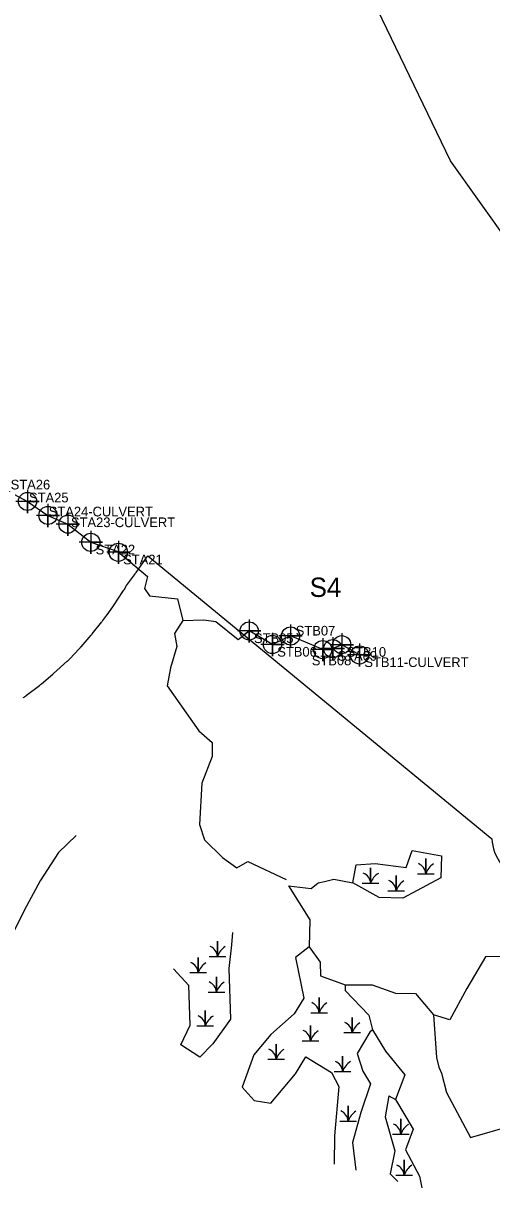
# Model space of a CAD drawing. Extents: x 1253697 to 1278588, y 912189 to 981699.
# Drawn here: x 1260180 to 1260665, y 913254 to 914458 of the extents above; entities that cross this region are included whole.
import ezdxf

# ---------------------------------------------------------------- set-up
doc = ezdxf.new("R2010")
doc.units = 0
for name, color, linetype in [('Default', 7, 'Continuous'), ('Exist Environmental Wetland Boundary', 7, 'Continuous'), ('Exist Environmental Wetland Boundary Cogo Number', 7, 'Continuous'), ('Exist Hydro Jurisdictional Stream or Body of Water Mitigable', 7, 'Continuous'), ('Exist Hydro Jurisdictional Stream or Body of Water Mitigable Cogo Comment', 7, 'Continuous'), ('Exist Hydro Jurisdictional Stream or Body of Water Mitigable Cogo Point CELL', 7, 'Continuous'), ('Exist Hydro Swamp or Marsh', 7, 'Continuous')]:
    doc.layers.add(name, color=color, linetype=linetype)

msp = doc.modelspace()

# ---------------------------------------------------------------- linework, layer by layer
at = {"layer": 'Default'}
for p, q in [((1260273.8, 913856.5), (1260282.9, 913870.4)), ((1260273.8, 913856.5), (1260282.9, 913870.4)), ((1260273.8, 913856.5), (1260282.9, 913870.4)), ((1260273.8, 913856.5), (1260282.9, 913870.4)), ((1260262.1, 913840.4), (1260266.1, 913845.8)), ((1260262.1, 913840.4), (1260266.1, 913845.8)), ((1260262.1, 913840.4), (1260266.1, 913845.8)), ((1260262.1, 913840.4), (1260266.1, 913845.8)), ((1260266.4, 913846.3), (1260272.4, 913854.5)), ((1260266.4, 913846.3), (1260272.4, 913854.5)), ((1260266.4, 913846.3), (1260272.4, 913854.5)), ((1260266.4, 913846.3), (1260272.4, 913854.5)), ((1260251.1, 913826.6), (1260261.1, 913839.1)), ((1260251.1, 913826.6), (1260261.1, 913839.1)), ((1260251.1, 913826.6), (1260261.1, 913839.1)), ((1260251.1, 913826.6), (1260261.1, 913839.1)), ((1260239.6, 913813.1), (1260249.9, 913825.2)), ((1260239.6, 913813.1), (1260249.9, 913825.2)), ((1260239.6, 913813.1), (1260249.9, 913825.2)), ((1260239.6, 913813.1), (1260249.9, 913825.2)), ((1260227.8, 913800.7), (1260237.7, 913811.1)), ((1260227.8, 913800.7), (1260237.7, 913811.1)), ((1260227.8, 913800.7), (1260237.7, 913811.1)), ((1260227.8, 913800.7), (1260237.7, 913811.1)), ((1260211, 913785.5), (1260225, 913798.1)), ((1260211, 913785.5), (1260225, 913798.1)), ((1260211, 913785.5), (1260225, 913798.1)), ((1260211, 913785.5), (1260225, 913798.1)), ((1260198.5, 913774.8), (1260210.2, 913784.8)), ((1260198.5, 913774.8), (1260210.2, 913784.8)), ((1260198.5, 913774.8), (1260210.2, 913784.8)), ((1260198.5, 913774.8), (1260210.2, 913784.8)), ((1260183.2, 913763), (1260196.4, 913773.2)), ((1260183.2, 913763), (1260196.4, 913773.2)), ((1260183.2, 913763), (1260196.4, 913773.2)), ((1260183.2, 913763), (1260196.4, 913773.2))]:
    msp.add_line(p, q, dxfattribs=at)
for points in [[(1261126.9, 913832.3), (1260885, 914025.7), (1260783.1, 914115.2), (1260719.8, 914184.5), (1260681.8, 914231.6), (1260621.8, 914315.9), (1260490.2, 914589.2), (1260463.9, 914685.8), (1260447.7, 914764), (1260445.4, 914777.7), (1260444.3, 914785.1), (1260438.9, 914823.1), (1260433.3, 914875.8), (1260429.6, 914955.5), (1260430.1, 914996.6), (1260457.3, 915231.6)], [(1261126.9, 913832.3), (1260885, 914025.7), (1260783.1, 914115.2), (1260719.8, 914184.5), (1260681.8, 914231.6), (1260621.8, 914315.9), (1260490.2, 914589.2), (1260463.9, 914685.8), (1260447.7, 914764), (1260445.4, 914777.7), (1260444.3, 914785.1), (1260438.9, 914823.1), (1260433.3, 914875.8), (1260429.6, 914955.5), (1260430.1, 914996.6), (1260457.3, 915231.6)], [(1261126.9, 913832.3), (1260885, 914025.7), (1260783.1, 914115.2), (1260719.8, 914184.5), (1260681.8, 914231.6), (1260621.8, 914315.9), (1260490.2, 914589.2), (1260463.9, 914685.8), (1260447.7, 914764), (1260445.4, 914777.7), (1260444.3, 914785.1), (1260438.9, 914823.1), (1260433.3, 914875.8), (1260429.6, 914955.5), (1260430.1, 914996.6), (1260457.3, 915231.6)], [(1261126.9, 913832.3), (1260885, 914025.7), (1260783.1, 914115.2), (1260719.8, 914184.5), (1260681.8, 914231.6), (1260621.8, 914315.9), (1260490.2, 914589.2), (1260463.9, 914685.8), (1260447.7, 914764), (1260445.4, 914777.7), (1260444.3, 914785.1), (1260438.9, 914823.1), (1260433.3, 914875.8), (1260429.6, 914955.5), (1260430.1, 914996.6), (1260457.3, 915231.6)], [(1260296.5, 913890), (1260308.6, 913907.1), (1260664.5, 913614.5)], [(1260296.5, 913890), (1260308.6, 913907.1), (1260664.5, 913614.5)], [(1260296.5, 913890), (1260308.6, 913907.1), (1260664.5, 913614.5)], [(1260296.5, 913890), (1260308.6, 913907.1), (1260664.5, 913614.5)], [(1260284, 913872.1), (1260286.6, 913876.6), (1260295.9, 913889.1)], [(1260284, 913872.1), (1260286.6, 913876.6), (1260295.9, 913889.1)], [(1260284, 913872.1), (1260286.6, 913876.6), (1260295.9, 913889.1)], [(1260284, 913872.1), (1260286.6, 913876.6), (1260295.9, 913889.1)]]:
    msp.add_lwpolyline(points, dxfattribs=at)
for centre, start, end in [((1260255.7, 913918.9), 323.5537, 324.7668), ((1260255.7, 913918.9), 323.5537, 324.7668), ((1260255.7, 913918.9), 323.5537, 324.7668), ((1260255.7, 913918.9), 323.5537, 324.7668), ((1260241, 913897.8), 326.8185, 329.1489), ((1260241, 913897.8), 326.8185, 329.1489), ((1260241, 913897.8), 326.8185, 329.1489), ((1260241, 913897.8), 326.8185, 329.1489), ((1260226, 913875.7), 323.3471, 323.9808), ((1260226, 913875.7), 323.3471, 323.9808), ((1260226, 913875.7), 323.3471, 323.9808), ((1260226, 913875.7), 323.3471, 323.9808), ((1260231.9, 913883.9), 323.9808, 326.8185), ((1260231.9, 913883.9), 323.9808, 326.8185), ((1260231.9, 913883.9), 323.9808, 326.8185), ((1260231.9, 913883.9), 323.9808, 326.8185), ((1260221.9, 913870.3), 321.4621, 323.3471), ((1260221.9, 913870.3), 321.4621, 323.3471), ((1260221.9, 913870.3), 321.4621, 323.3471), ((1260221.9, 913870.3), 321.4621, 323.3471), ((1260212, 913857.8), 319.3323, 321.4621), ((1260212, 913857.8), 319.3323, 321.4621), ((1260212, 913857.8), 319.3323, 321.4621), ((1260212, 913857.8), 319.3323, 321.4621), ((1260201.6, 913845.7), 316.2099, 319.3323), ((1260201.6, 913845.7), 316.2099, 319.3323), ((1260201.6, 913845.7), 316.2099, 319.3323), ((1260201.6, 913845.7), 316.2099, 319.3323), ((1260191.7, 913835.3), 311.8111, 316.2099), ((1260191.7, 913835.3), 311.8111, 316.2099), ((1260191.7, 913835.3), 311.8111, 316.2099), ((1260191.7, 913835.3), 311.8111, 316.2099), ((1260166, 913812.9), 307.4467, 310.5316), ((1260166, 913812.9), 307.4467, 310.5316), ((1260166, 913812.9), 307.4467, 310.5316), ((1260166, 913812.9), 307.4467, 310.5316), ((1260177.7, 913822.8), 310.5316, 311.8111), ((1260177.7, 913822.8), 310.5316, 311.8111), ((1260177.7, 913822.8), 310.5316, 311.8111), ((1260177.7, 913822.8), 310.5316, 311.8111), ((1260152.8, 913802.7), 302.5799, 307.4467), ((1260152.8, 913802.7), 302.5799, 307.4467), ((1260152.8, 913802.7), 302.5799, 307.4467), ((1260152.8, 913802.7), 302.5799, 307.4467), ((1260714.4, 913618.1), 184.1324, 216.2345), ((1260714.4, 913618.1), 184.1324, 216.2345), ((1260714.4, 913618.1), 184.1324, 216.2345), ((1260714.4, 913618.1), 184.1324, 216.2345)]:
    msp.add_arc(centre, 50, start, end, dxfattribs=at)
at = {"layer": 'Exist Environmental Wetland Boundary'}
msp.add_lwpolyline([(1260524.1, 913587.6), (1260543.9, 913589.1), (1260575.8, 913584.8), (1260582.1, 913602.3), (1260597.3, 913599.8), (1260612.4, 913596.8), (1260611.8, 913574), (1260572.5, 913553), (1260548.1, 913553.7), (1260520.8, 913568.8)], close=True, dxfattribs=at)
for points in [[(1260396.1, 913517.6), (1260395.3, 913504.9), (1260392.5, 913480.4), (1260394.2, 913428), (1260375.9, 913402.5), (1260362.6, 913388.6), (1260342.9, 913401.5), (1260352.3, 913421.9), (1260351.2, 913462.9), (1260335.2, 913479.9)], [(1260475.5, 913502.8), (1260461.4, 913491.8), (1260470.1, 913449.8), (1260460.1, 913433.4), (1260436, 913412), (1260418.2, 913391), (1260406.2, 913357.6), (1260418.6, 913343.8), (1260436, 913341), (1260461.5, 913371.4), (1260472, 913388.9), (1260498.6, 913372.7), (1260506.3, 913358.3), (1260501.7, 913307.2), (1260501.5, 913277.9)], [(1260475.5, 913502.8), (1260486.9, 913487), (1260487.3, 913472.9), (1260512.9, 913463.5), (1260512.7, 913457.6), (1260537.3, 913432.2), (1260541.1, 913416.8), (1260538.4, 913414.5), (1260525.2, 913392.6), (1260531.2, 913374), (1260539.2, 913361.1), (1260529.1, 913331.4), (1260520.5, 913300.3), (1260523.8, 913271.9)], [(1260558.1, 913348.8), (1260554.3, 913326.9), (1260564.2, 913291.8), (1260559.3, 913268.1), (1260567.4, 913260.2)], [(1260558.1, 913348.8), (1260565.1, 913344.9), (1260583.2, 913314.3), (1260575.4, 913292.7), (1260589.6, 913265.6), (1260592.2, 913253.6)]]:
    msp.add_lwpolyline(points, dxfattribs=at)
at = {"layer": 'Exist Hydro Jurisdictional Stream or Body of Water Mitigable'}
msp.add_line((1260226.5, 913939.5), (1260225.9, 913940), dxfattribs=at)
for points in [[(1259903.1, 914152.4), (1259926.1, 914135.1), (1259928.5, 914122.8), (1259949.5, 914108.7), (1259980.6, 914083.6), (1260018, 914066.7), (1260046.6, 914049.7), (1260057.3, 914045.6), (1260102.1, 914011.9), (1260111.8, 914005.5), (1260128.8, 913997.3), (1260160.9, 913975.8), (1260184.1, 913963.5), (1260205.3, 913949), (1260226.5, 913939.5)], [(1260225.9, 913940), (1260249.6, 913921.2), (1260277.7, 913911.8), (1260299.1, 913893.7)], [(1260225.9, 913940), (1260249.6, 913921.2), (1260277.7, 913911.8), (1260308.2, 913886), (1260305.3, 913873.4), (1260310.3, 913865.9), (1260339.2, 913862.6), (1260344.8, 913840.2), (1260366.7, 913841.1), (1260379, 913839.2), (1260402.2, 913820.8), (1260413.5, 913829.5)], [(1260344.8, 913840.2), (1260336.3, 913826.9), (1260338.6, 913813.4), (1260332.1, 913791.2), (1260328.7, 913772.7), (1260361.3, 913726.3), (1260375.2, 913714.1), (1260375.2, 913699.8), (1260364.6, 913672), (1260362.2, 913629.3), (1260367.3, 913613.5), (1260385.9, 913595.1), (1260400.9, 913584.4), (1260412.1, 913590.9), (1260451.7, 913572.3)], [(1260527.7, 913804.7), (1260509.3, 913815.3), (1260500, 913811.2), (1260489.6, 913810.2), (1260456.3, 913824.3), (1260437.6, 913815.5), (1260413.5, 913829.5), (1260408.1, 913825.3)], [(1260234.6, 913618.1), (1260216.1, 913600.4), (1260197.1, 913571.1), (1260180.6, 913540.3), (1260165.8, 913510.5), (1260157.4, 913474.6), (1260147.6, 913437.2), (1260126.5, 913405.4), (1260109.1, 913382.8)], [(1260454.1, 913565.7), (1260477.7, 913563.2), (1260484.8, 913569), (1260491.5, 913570.4), (1260501.2, 913572.9), (1260520.8, 913568.8)], [(1260454.1, 913565.7), (1260476.4, 913530.7), (1260475.5, 913502.8), (1260486.9, 913487), (1260487.3, 913472.9), (1260512.9, 913463.5), (1260540.9, 913463.4), (1260565, 913454.8), (1260585.6, 913454.5), (1260604.3, 913432.3), (1260607.2, 913388.4), (1260609.8, 913378.3), (1260612.6, 913372.1), (1260617.6, 913352.2), (1260642.4, 913305.6), (1260685.8, 913317.8), (1260734.5, 913312.3), (1260786.9, 913302.3), (1260809.8, 913272)], [(1260774.9, 913564.6), (1260768.5, 913557.3), (1260740.4, 913548.2), (1260720.4, 913537.4), (1260696.9, 913522.2), (1260688.7, 913492.8), (1260658.1, 913492.3), (1260638.7, 913459.6), (1260621, 913427.1), (1260604.3, 913432.3)], [(1260512.7, 913457.6), (1260537.3, 913432.2), (1260541.1, 913416.8), (1260554.5, 913395), (1260574.5, 913370.4), (1260565.1, 913344.9)], [(1260541.1, 913416.8), (1260538.4, 913414.5), (1260525.2, 913392.6), (1260531.2, 913374)]]:
    msp.add_lwpolyline(points, dxfattribs=at)
at = {"layer": 'Exist Hydro Jurisdictional Stream or Body of Water Mitigable Cogo Point CELL'}
for points in [[(1260184.1, 913975.5), (1260184.1, 913951.5), (1260184.1, 913963.5), (1260196.1, 913963.5), (1260172.1, 913963.5)], [(1260184.1, 913975.5), (1260184.1, 913951.5), (1260184.1, 913963.5), (1260196.1, 913963.5), (1260172.1, 913963.5)], [(1260205.3, 913961), (1260205.3, 913937), (1260205.3, 913949), (1260217.3, 913949), (1260193.3, 913949)], [(1260205.3, 913961), (1260205.3, 913937), (1260205.3, 913949), (1260217.3, 913949), (1260193.3, 913949)], [(1260225.9, 913952), (1260225.9, 913928), (1260225.9, 913940), (1260237.9, 913940), (1260213.9, 913940)], [(1260225.9, 913952), (1260225.9, 913928), (1260225.9, 913940), (1260237.9, 913940), (1260213.9, 913940)], [(1260249.6, 913933.2), (1260249.6, 913909.2), (1260249.6, 913921.2), (1260261.6, 913921.2), (1260237.6, 913921.2)], [(1260249.6, 913933.2), (1260249.6, 913909.2), (1260249.6, 913921.2), (1260261.6, 913921.2), (1260237.6, 913921.2)], [(1260278.1, 913922.9), (1260278.1, 913898.9), (1260278.1, 913910.9), (1260290.1, 913910.9), (1260266.1, 913910.9)], [(1260278.1, 913922.9), (1260278.1, 913898.9), (1260278.1, 913910.9), (1260290.1, 913910.9), (1260266.1, 913910.9)], [(1260413.5, 913841.5), (1260413.5, 913817.5), (1260413.5, 913829.5), (1260425.5, 913829.5), (1260401.5, 913829.5)], [(1260456.3, 913836.3), (1260456.3, 913812.3), (1260456.3, 913824.3), (1260468.3, 913824.3), (1260444.3, 913824.3)], [(1260437.6, 913827.5), (1260437.6, 913803.5), (1260437.6, 913815.5), (1260449.6, 913815.5), (1260425.6, 913815.5)], [(1260489.6, 913822.2), (1260489.6, 913798.2), (1260489.6, 913810.2), (1260501.6, 913810.2), (1260477.6, 913810.2)], [(1260500, 913823.2), (1260500, 913799.2), (1260500, 913811.2), (1260512, 913811.2), (1260488, 913811.2)], [(1260509.3, 913827.3), (1260509.3, 913803.3), (1260509.3, 913815.3), (1260521.3, 913815.3), (1260497.3, 913815.3)], [(1260527.7, 913816.7), (1260527.7, 913792.7), (1260527.7, 913804.7), (1260539.7, 913804.7), (1260515.7, 913804.7)]]:
    msp.add_lwpolyline(points, dxfattribs=at)
for centre in [(1260184.1, 913963.5), (1260184.1, 913963.5), (1260205.3, 913949), (1260205.3, 913949), (1260225.9, 913940), (1260225.9, 913940), (1260249.6, 913921.2), (1260249.6, 913921.2), (1260278.1, 913910.9), (1260278.1, 913910.9), (1260413.5, 913829.5), (1260437.6, 913815.5), (1260456.3, 913824.3), (1260509.3, 913815.3), (1260489.6, 913810.2), (1260500, 913811.2), (1260527.7, 913804.7)]:
    msp.add_circle(centre, 9.38, dxfattribs=at)
at = {"layer": 'Exist Hydro Swamp or Marsh'}
for p, q in [((1260596.3, 913585.5), (1260596.3, 913585.5)), ((1260539.2, 913575.7), (1260539.2, 913575.7)), ((1260565.6, 913568), (1260565.6, 913568)), ((1260380.7, 913499.9), (1260380.7, 913499.9)), ((1260360.7, 913483.2), (1260360.7, 913483.2)), ((1260379.6, 913463.1), (1260379.6, 913463.1)), ((1260485.8, 913441.8), (1260485.8, 913441.8)), ((1260368.1, 913428.1), (1260368.1, 913428.1)), ((1260476.9, 913412.8), (1260476.9, 913412.8)), ((1260520, 913421.1), (1260520, 913421.1)), ((1260441.4, 913393.6), (1260441.4, 913393.6)), ((1260510.2, 913381), (1260510.2, 913381)), ((1260516, 913329.6), (1260516, 913329.6)), ((1260570.4, 913316.1), (1260570.4, 913316.1)), ((1260573.9, 913273.7), (1260573.9, 913273.7))]:
    msp.add_line(p, q, dxfattribs=at)
for points in [[(1260587.7, 913578.3), (1260596.3, 913578.3), (1260596.3, 913594.1), (1260596.3, 913578.3), (1260604.9, 913578.3)], [(1260530.6, 913568.6), (1260539.2, 913568.6), (1260539.2, 913584.4), (1260539.2, 913568.6), (1260547.8, 913568.6)], [(1260557, 913560.8), (1260565.6, 913560.8), (1260565.6, 913576.6), (1260565.6, 913560.8), (1260574.2, 913560.8)], [(1260372.1, 913492.7), (1260380.7, 913492.7), (1260380.7, 913508.5), (1260380.7, 913492.7), (1260389.3, 913492.7)], [(1260352.1, 913476.1), (1260360.7, 913476.1), (1260360.7, 913491.9), (1260360.7, 913476.1), (1260369.3, 913476.1)], [(1260371, 913456), (1260379.6, 913456), (1260379.6, 913471.8), (1260379.6, 913456), (1260388.2, 913456)], [(1260477.2, 913434.6), (1260485.8, 913434.6), (1260485.8, 913450.4), (1260485.8, 913434.6), (1260494.4, 913434.6)], [(1260359.5, 913421), (1260368.1, 913421), (1260368.1, 913436.8), (1260368.1, 913421), (1260376.7, 913421)], [(1260511.4, 913414), (1260520, 913414), (1260520, 913429.8), (1260520, 913414), (1260528.6, 913414)], [(1260468.3, 913405.7), (1260477, 913405.7), (1260477, 913421.4), (1260477, 913405.7), (1260485.6, 913405.7)], [(1260432.8, 913386.4), (1260441.4, 913386.4), (1260441.4, 913402.2), (1260441.4, 913386.4), (1260450, 913386.4)], [(1260501.6, 913373.8), (1260510.2, 913373.8), (1260510.2, 913389.6), (1260510.2, 913373.8), (1260518.8, 913373.8)], [(1260507.4, 913322.5), (1260516, 913322.5), (1260516, 913338.3), (1260516, 913322.5), (1260524.6, 913322.5)], [(1260561.8, 913309), (1260570.4, 913309), (1260570.4, 913324.8), (1260570.4, 913309), (1260579, 913309)], [(1260565.3, 913266.5), (1260573.9, 913266.5), (1260573.9, 913282.3), (1260573.9, 913266.5), (1260582.5, 913266.5)]]:
    msp.add_lwpolyline(points, dxfattribs=at)
for centre, radius, start, end in [((1260584, 913577.5), 12.3, 4.1403, 67.535), ((1260614.5, 913572.3), 19.2, 122.1274, 161.6222), ((1260526.9, 913567.7), 12.3, 4.1403, 67.535), ((1260557.4, 913562.5), 19.2, 122.1274, 161.6222), ((1260553.3, 913560), 12.3, 4.1403, 67.535), ((1260583.8, 913554.8), 19.2, 122.1274, 161.6222), ((1260368.5, 913491.8), 12.3, 4.1403, 67.535), ((1260399, 913486.7), 19.2, 122.1274, 161.6222), ((1260348.4, 913475.2), 12.3, 4.1403, 67.535), ((1260378.9, 913470), 19.2, 122.1274, 161.6222), ((1260367.3, 913455.1), 12.3, 4.1403, 67.535), ((1260397.8, 913449.9), 19.2, 122.1274, 161.6222), ((1260473.6, 913433.7), 12.3, 4.1403, 67.535), ((1260504.1, 913428.6), 19.2, 122.1274, 161.6222), ((1260355.9, 913420.1), 12.3, 4.1403, 67.535), ((1260386.4, 913414.9), 19.2, 122.1274, 161.6222), ((1260507.7, 913413.1), 12.3, 4.1403, 67.535), ((1260464.7, 913404.8), 12.3, 4.1403, 67.535), ((1260495.2, 913399.6), 19.2, 122.1274, 161.6222), ((1260538.2, 913407.9), 19.2, 122.1274, 161.6222), ((1260429.1, 913385.6), 12.3, 4.1403, 67.535), ((1260459.6, 913380.4), 19.2, 122.1274, 161.6222), ((1260498, 913372.9), 12.3, 4.1403, 67.535), ((1260528.5, 913367.8), 19.2, 122.1274, 161.6222), ((1260503.7, 913321.6), 12.3, 4.1403, 67.535), ((1260534.2, 913316.4), 19.2, 122.1274, 161.6222), ((1260558.2, 913308.1), 12.3, 4.1403, 67.535), ((1260588.7, 913302.9), 19.2, 122.1274, 161.6222), ((1260561.6, 913265.6), 12.3, 4.1403, 67.535), ((1260592.1, 913260.5), 19.2, 122.1274, 161.6222)]:
    msp.add_arc(centre, radius, start, end, dxfattribs=at)

# ---------------------------------------------------------------- texts
at = {"layer": 'Exist Environmental Wetland Boundary Cogo Number'}
msp.add_text('S4', height=20, dxfattribs=at).set_placement((1260476.1, 913864.7))
at = {"layer": 'Exist Hydro Jurisdictional Stream or Body of Water Mitigable Cogo Comment'}
for s, p in [('STA26', (1260166.7, 913975.9)), ('STA25', (1260185.7, 913962.5)), ('STA24-CULVERT', (1260206.1, 913948)), ('STA23-CULVERT', (1260229.1, 913936.9)), ('STA22', (1260254.6, 913908.7)), ('STA21', (1260283.1, 913898.4)), ('STB07', (1260461.7, 913824.8)), ('STB05', (1260418.5, 913817)), ('STB06', (1260442.6, 913803)), ('STB10', (1260514.3, 913802.8)), ('STB08', (1260478.3, 913794)), ('STA09', (1260505, 913798.7)), ('STB11-CULVERT', (1260532.7, 913792.2))]:
    msp.add_text(s, height=10, dxfattribs=at).set_placement(p)

doc.saveas('drawing.dxf')
